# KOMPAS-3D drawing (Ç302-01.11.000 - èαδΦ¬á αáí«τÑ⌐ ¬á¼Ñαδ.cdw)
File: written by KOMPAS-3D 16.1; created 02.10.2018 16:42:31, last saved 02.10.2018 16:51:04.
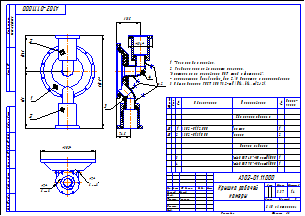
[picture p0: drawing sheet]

Sheet 1: A3, landscape

Title block, sheet 1: name: Крышка рабочей / камеры; designation: А302-01.11.000; mass: 3,37; scale: 1:4; sheets: 1; organisation: ЗАО «Астерион»; sheet format: A3; stored path: \\192.168.87.28\Konstructor_doc\Мембранные насосы\Мембранный электропривод\А302-00.00.000 - ASTRA-302 (МЭ200)\3Д ПВХ\А302-01.11.000 - Крышка рабочей камеры.cdw; drawn by: Милов; technical control: Лучихин

Views: Вид 1, Местный разрез 1, Спереди, Проекционный вид 2, Проекционный вид 3, Вид:1
Referenced files in \\192.168.87.28\Konstructor_doc\Мембранные насосы\Мембранный электропривод\А302-00.00.000 - ASTRA-302 (МЭ200)\3Д ПВХ\: А302-01.12.001 - Крышка.m3d, А302-01.31.001 - Корпус.m3d, А302-01.12.000 - Крышка.cdw, А302-01.31.000 - Корпус.cdw, А302-01.12.000 - Крышка.a3d, А302-01.31.000 - Корпус.a3d
Referenced files in Z:\Мембранные насосы\Мембранный электропривод\А302-00.00.000 - ASTRA-302 (МЭ200)\3Д ПВХ\Отработка\: Отвод ПВХ 45гр 50 арт.HIV050.m3d, Отвод ПВХ 90гр 50 арт.GIV050.m3d
Referenced files in \\192.168.87.28\Konstructor_doc\Мембранные насосы\Мембранный электропривод\А302-00.00.000 - ASTRA-302 (МЭ200)\3Д ПВХ\Отработка\: Труба ПВХ PN10 50х2,4.m3d
Referenced files in Z:\Мембранные насосы\Мембранный электропривод\А302-00.00.000 - ASTRA-302 (МЭ200)\3Д ПВХ\: А302-01.11.000 - Крышка рабочей камеры.a3d
Referenced files: graphic.tdp
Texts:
  *Размеры для справок.
  Разделку кромок выполнить согласно:
  "Инструкция по склеиванию ПВХ труб и фитингов".
  - расположение Konstructor_doc Z:\5 Оснастка и приспособления
  Общие допуски ГОСТ 30893.2-mK (H14, h14,  t2/2).
  Крышка
  Корпус
  Отвод ПВХ 90   50 арт.GIV050
  Отвод ПВХ 90@1~ @2~50 арт.GIV050
  Отвод ПВХ 45   50 арт.HIV050
  Отвод ПВХ 45@1~ @2~50 арт.HIV050
  Лит-Масса-Масштаб
  Материал-Предприятие
  Title Specification
  Body Specification ( left align )
  Body Specificaton ( centered )
  Поз.
  Кол.
  Приме-
  чание
  Таблица спецификации
  Труба ПВХ PN10 50х2,4
  Отвод ПВХ 90гр 50 арт.GIV050
  Отвод ПВХ 45гр 50 арт.HIV050
Dimensions and other numbers on the sheet: 131,5; 134; 74,5; 3; 4; 318; 194,5; 512,5; 1; 2; 302; 7; 6 отв.; 1:4; 3,37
